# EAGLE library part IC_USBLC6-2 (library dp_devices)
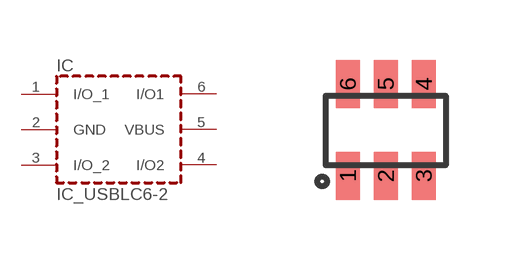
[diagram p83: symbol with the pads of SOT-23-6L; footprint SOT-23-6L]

Designator prefix IC

## IC_USBLC6-2  [SOT-23-6L]
1  I/O_1
2  GND
3  I/O_2
4  I/O2
5  VBUS
6  I/O1

## Footprint SOT-23-6L (pad centres in mm)
smd 0.6 x 1.2: 1 -0.95,-2.3; 2 0,-2.3; 3 0.95,-2.3; 4 0.95,0; 5 0,0; 6 -0.95,0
